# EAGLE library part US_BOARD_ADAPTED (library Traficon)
Board for US-racks, but with an 3x16pins DIN41612F connector
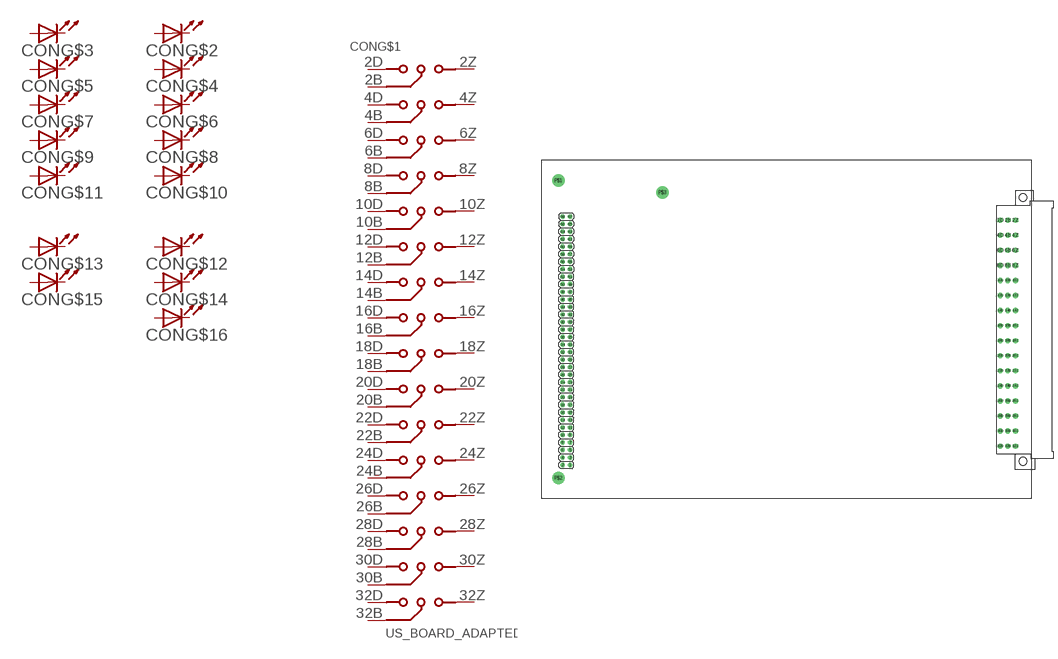
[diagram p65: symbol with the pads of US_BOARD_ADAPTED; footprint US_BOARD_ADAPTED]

Designator prefix CON; gates G$1=DIN41612-F G$2=LED-2 G$3=LED-2 G$4=LED-2 G$5=LED-2 G$6=LED-2 G$7=LED-2 G$8=LED-2 G$9=LED-2 G$10=LED-2 G$11=LED-2 G$12=LED-2 G$13=LED-2 G$14=LED-2 G$15=LED-2 G$16=LED-2 G$17=LED-2 G$18=LED-2 G$19=LED-2 G$20=LED-2 G$21=LED-2 G$22=LED-2 G$23=LED-2 G$24=LED-2 G$25=LED-2 G$26=LED-2 G$27=LED-2 G$28=LED-2 G$29=LED-2 G$30=LED-2 G$31=LED-2 G$32=LED-2 G$33=LED-2 G$34=LED-2 G$35=LED-2 G$36=PE G$37=PE G$38=PE

## US_BOARD_ADAPTED  [US_BOARD_ADAPTED]
1  G$2:A  pas
2  G$3:A  pas
2B  G$1:2B
2D  G$1:2D
2Z  G$1:2Z
3  G$2:C  pas
4  G$3:C  pas
4B  G$1:4B
4D  G$1:4D
4Z  G$1:4Z
5  G$4:A  pas
6  G$5:A  pas
6B  G$1:6B
6D  G$1:6D
6Z  G$1:6Z
7  G$4:C  pas
8  G$5:C  pas
8B  G$1:8B
8D  G$1:8D
8Z  G$1:8Z
9  G$6:A  pas
10  G$7:A  pas
10B  G$1:10B
10D  G$1:10D
10Z  G$1:10Z
11  G$6:C  pas
12  G$7:C  pas
12B  G$1:12B
12D  G$1:12D
12Z  G$1:12Z
13  G$8:A  pas
14  G$9:A  pas
14B  G$1:14B
14D  G$1:14D
14Z  G$1:14Z
15  G$8:C  pas
16  G$9:C  pas
16B  G$1:16B
16D  G$1:16D
16Z  G$1:16Z
17  G$10:A  pas
18  G$11:A  pas
18B  G$1:18B
18D  G$1:18D
18Z  G$1:18Z
19  G$10:C  pas
20  G$11:C  pas
20B  G$1:20B
20D  G$1:20D
20Z  G$1:20Z
21  G$12:A  pas
22  G$13:A  pas
22B  G$1:22B
22D  G$1:22D
22Z  G$1:22Z
23  G$12:C  pas
24  G$13:C  pas
24B  G$1:24B
24D  G$1:24D
24Z  G$1:24Z
25  G$14:A  pas
26  G$15:A  pas
26B  G$1:26B
26D  G$1:26D
26Z  G$1:26Z
27  G$14:C  pas
28  G$15:C  pas
28B  G$1:28B
28D  G$1:28D
28Z  G$1:28Z
29  G$16:A  pas
30  G$17:A  pas
30B  G$1:30B
30D  G$1:30D
30Z  G$1:30Z
31  G$16:C  pas
32  G$17:C  pas
32B  G$1:32B
32D  G$1:32D
32Z  G$1:32Z
33  G$18:A  pas
34  G$19:A  pas
35  G$18:C  pas
36  G$19:C  pas
37  G$20:A  pas
38  G$21:A  pas
39  G$20:C  pas
40  G$21:C  pas
41  G$22:A  pas
42  G$23:A  pas
43  G$22:C  pas
44  G$23:C  pas
45  G$24:A  pas
46  G$25:A  pas
47  G$24:C  pas
48  G$25:C  pas
49  G$26:A  pas
50  G$27:A  pas
51  G$26:C  pas
52  G$27:C  pas
53  G$28:A  pas
54  G$29:A  pas
55  G$28:C  pas
56  G$29:C  pas
57  G$30:A  pas
58  G$31:A  pas
59  G$30:C  pas
60  G$31:C  pas
61  G$32:A  pas
62  G$33:A  pas
63  G$32:C  pas
64  G$33:C  pas
65  G$34:A  pas
66  G$35:A  pas
67  G$34:C  pas
68  G$35:C  pas
P$1  G$36:PE  sup
P$2  G$37:PE  sup
P$3  G$38:PE  sup

## Footprint US_BOARD_ADAPTED (pad centres in mm)
drill 1.016 octagon: 1 12.525,11.43; 2 9.985,11.43; 3 12.525,13.97; 4 9.985,13.97; 5 12.525,16.51; 6 9.985,16.51; 7 12.525,19.05; 8 9.985,19.05; 9 12.525,21.59; 10 9.985,21.59; 11 12.525,24.13; 12 9.985,24.13; 13 12.525,26.67; 14 9.985,26.67; 15 12.525,29.21; 16 9.985,29.21; 17 12.525,31.75; 18 9.985,31.75; 19 12.525,34.29; 20 9.985,34.29; 21 12.525,36.83; 22 9.985,36.83; 23 12.525,39.37; 24 9.985,39.37; 25 12.525,41.91; 26 9.985,41.91; 27 12.525,44.45; 28 9.985,44.45; 29 12.525,46.99; 30 9.985,46.99; 31 12.525,49.53; 32 9.985,49.53; 33 12.525,52.07; 34 9.985,52.07; 35 12.525,54.61; 36 9.985,54.61; 37 12.525,57.15; 38 9.985,57.15; 39 12.525,59.69; 40 9.985,59.69; 41 12.525,62.23; 42 9.985,62.23; 43 12.525,64.77; 44 9.985,64.77; 45 12.525,67.31; 46 9.985,67.31; 47 12.525,69.85; 48 9.985,69.85; 49 12.525,72.39; 50 9.985,72.39; 51 12.525,74.93; 52 9.985,74.93; 53 12.525,77.47; 54 9.985,77.47; 55 12.525,80.01; 56 9.985,80.01; 57 12.525,82.55; 58 9.985,82.55; 59 12.525,85.09; 60 9.985,85.09; 61 12.525,87.63; 62 9.985,87.63; 63 12.525,90.17; 64 9.985,90.17; 65 12.525,92.71; 66 9.985,92.71; 67 12.525,95.25; 68 9.985,95.25
drill 1.016 pad 1.778 round: 2B 160.115,93.98; 2D 157.575,93.98; 2Z 162.655,93.98; 4B 160.115,88.9; 4D 157.575,88.9; 4Z 162.655,88.9; 6B 160.115,83.82; 6D 157.575,83.82; 6Z 162.655,83.82; 8B 160.115,78.74; 8D 157.575,78.74; 8Z 162.655,78.74; 10B 160.115,73.66; 10D 157.575,73.66; 10Z 162.655,73.66; 12B 160.115,68.58; 12D 157.575,68.58; 12Z 162.655,68.58; 14B 160.115,63.5; 14D 157.575,63.5; 14Z 162.655,63.5; 16B 160.115,58.42; 16D 157.575,58.42; 16Z 162.655,58.42; 18B 160.115,53.34; 18D 157.575,53.34; 18Z 162.655,53.34; 20B 160.115,48.26; 20D 157.575,48.26; 20Z 162.655,48.26; 22B 160.115,43.18; 22D 157.575,43.18; 22Z 162.655,43.18; 24B 160.115,38.1; 24D 157.575,38.1; 24Z 162.655,38.1; 26B 160.115,33.02; 26D 157.575,33.02; 26Z 162.655,33.02; 28B 160.115,27.94; 28D 157.575,27.94; 28Z 162.655,27.94; 30B 160.115,22.86; 30D 157.575,22.86; 30Z 162.655,22.86; 32B 160.115,17.78; 32D 157.575,17.78; 32Z 162.655,17.78
drill 3.2 round: P$1 8.57,107.36; P$2 8.57,7.03; P$3 43.64,103.35
hole 2.54 at 165.195,12.7
hole 2.54 at 165.195,101.6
